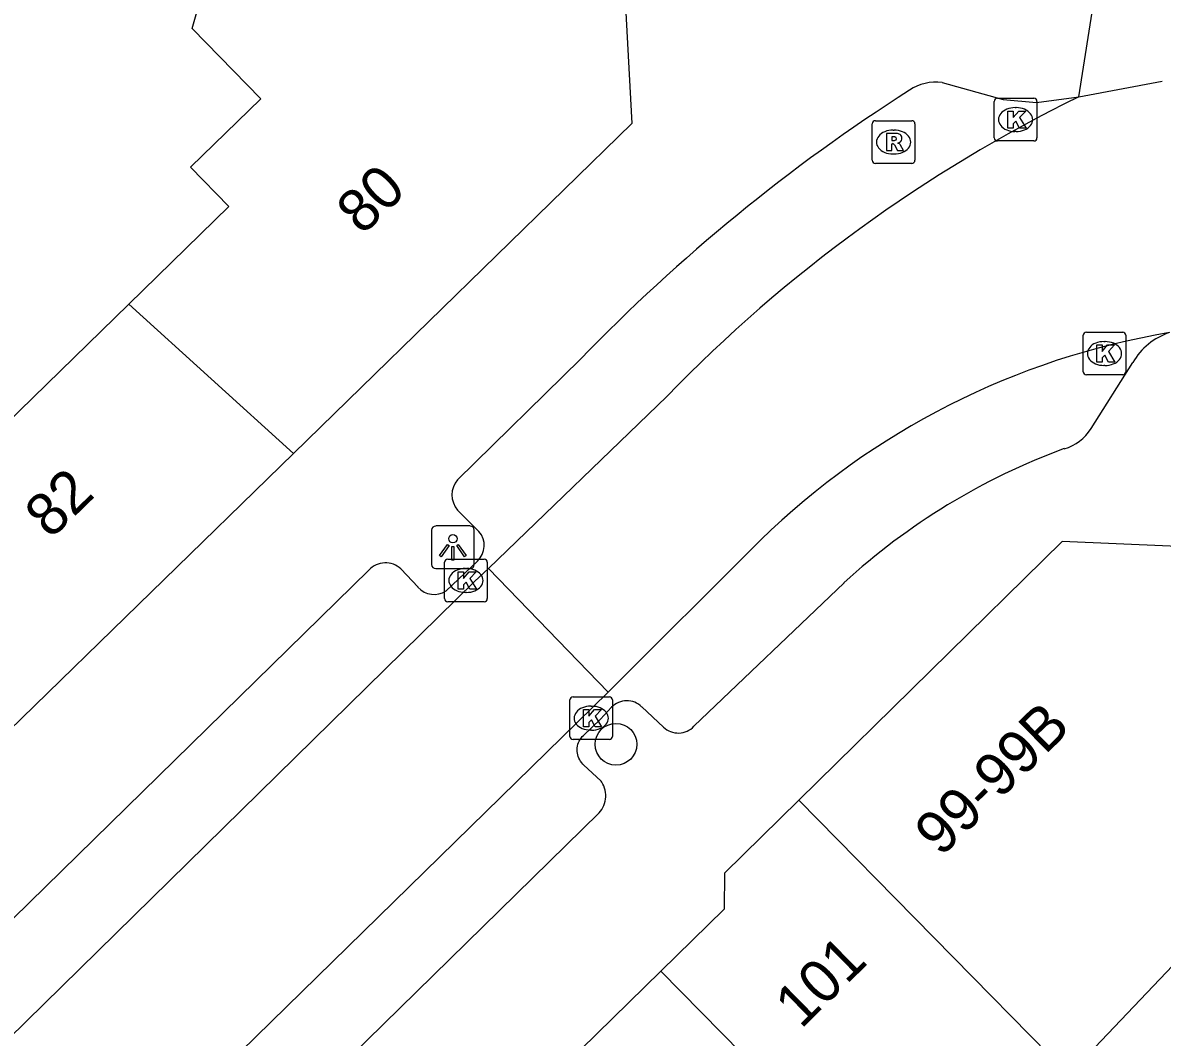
# Model space of a CAD drawing. Extents: x 160861 to 161308, y 384024 to 384878.
# Drawn here: x 161083.27 to 161109.96, y 384677.68 to 384701.45 of the extents above; entities that cross this region are included whole.
import ezdxf

# ---------------------------------------------------------------- set-up
doc = ezdxf.new("R2010")
doc.units = 0
for name, color, linetype in [('IMGEO_Boom', 7, 'Continuous'), ('IMGEO_Kolk', 7, 'Continuous'), ('IMGEO_Lichtpunt', 7, 'Continuous'), ('IMGEO_Pand', 7, 'Continuous'), ('IMGEO_Pand_nummerreeks', 7, 'Continuous'), ('IMGEO_Rijbaan_lokaal_gesloten', 7, 'Continuous'), ('IMGEO_Rijbaan_lokaal_open', 7, 'Continuous'), ('IMGEO_Rioolput', 7, 'Continuous'), ('IMGEO_Voetpad_open', 7, 'Continuous')]:
    doc.layers.add(name, color=color, linetype=linetype)

msp = doc.modelspace()

# ---------------------------------------------------------------- linework, layer by layer
at = {"layer": 'IMGEO_Boom'}
msp.add_circle((161097.165, 384684.545), 0.489, dxfattribs=at)
at = {"layer": 'IMGEO_Kolk'}
for p, q in [((161106.026, 384698.754), (161106.026, 384699.606)), ((161106.101, 384699.68), (161106.953, 384699.68)), ((161107.027, 384699.606), (161107.027, 384698.754)), ((161106.514, 384699.46), (161106.539, 384699.46)), ((161106.537, 384698.9), (161106.512, 384698.9)), ((161106.953, 384698.68), (161106.101, 384698.68)), ((161108.184, 384694.2), (161109.036, 384694.2)), ((161108.109, 384693.274), (161108.109, 384694.126)), ((161108.597, 384693.98), (161108.622, 384693.98)), ((161109.11, 384694.126), (161109.11, 384693.274)), ((161108.62, 384693.42), (161108.595, 384693.42)), ((161109.036, 384693.2), (161108.184, 384693.2)), ((161093.224, 384688.883), (161094.076, 384688.883)), ((161093.149, 384687.957), (161093.149, 384688.809)), ((161093.637, 384688.663), (161093.662, 384688.663)), ((161094.15, 384688.809), (161094.15, 384687.957)), ((161093.66, 384688.103), (161093.635, 384688.103)), ((161094.076, 384687.883), (161093.224, 384687.883)), ((161096.159, 384685.657), (161097.011, 384685.657)), ((161096.084, 384684.731), (161096.084, 384685.583)), ((161096.572, 384685.437), (161096.597, 384685.437)), ((161097.085, 384685.583), (161097.085, 384684.731)), ((161096.595, 384684.877), (161096.57, 384684.877)), ((161097.011, 384684.657), (161096.159, 384684.657))]:
    msp.add_line(p, q, dxfattribs=at)
for points in [[(161106.026, 384698.754), (161106.026, 384699.606)], [(161106.101, 384699.68), (161106.953, 384699.68)], [(161107.027, 384699.606), (161107.027, 384698.754)], [(161106.347, 384699.38), (161106.47, 384699.38), (161106.47, 384699.229), (161106.6, 384699.38), (161106.764, 384699.38), (161106.618, 384699.229), (161106.771, 384698.98), (161106.619, 384698.98), (161106.534, 384699.144), (161106.47, 384699.077), (161106.47, 384698.98), (161106.347, 384698.98), (161106.347, 384699.38)], [(161106.953, 384698.68), (161106.101, 384698.68)], [(161108.184, 384694.2), (161109.036, 384694.2)], [(161108.109, 384693.274), (161108.109, 384694.126)], [(161109.11, 384694.126), (161109.11, 384693.274)], [(161108.43, 384693.9), (161108.553, 384693.9), (161108.553, 384693.749), (161108.683, 384693.9), (161108.847, 384693.9), (161108.701, 384693.749), (161108.854, 384693.5), (161108.702, 384693.5), (161108.617, 384693.664), (161108.553, 384693.597), (161108.553, 384693.5), (161108.43, 384693.5), (161108.43, 384693.9)], [(161109.036, 384693.2), (161108.184, 384693.2)], [(161093.224, 384688.883), (161094.076, 384688.883)], [(161093.149, 384687.957), (161093.149, 384688.809)], [(161093.47, 384688.583), (161093.593, 384688.583), (161093.593, 384688.432), (161093.723, 384688.583), (161093.887, 384688.583), (161093.741, 384688.432), (161093.894, 384688.183), (161093.742, 384688.183), (161093.657, 384688.347), (161093.593, 384688.28), (161093.593, 384688.183), (161093.47, 384688.183), (161093.47, 384688.583)], [(161094.15, 384688.809), (161094.15, 384687.957)], [(161094.076, 384687.883), (161093.224, 384687.883)], [(161096.159, 384685.657), (161097.011, 384685.657)], [(161096.084, 384684.731), (161096.084, 384685.583)], [(161097.085, 384685.583), (161097.085, 384684.731)], [(161096.405, 384685.357), (161096.528, 384685.357), (161096.528, 384685.206), (161096.658, 384685.357), (161096.822, 384685.357), (161096.676, 384685.206), (161096.829, 384684.957), (161096.677, 384684.957), (161096.592, 384685.121), (161096.528, 384685.054), (161096.528, 384684.957), (161096.405, 384684.957), (161096.405, 384685.357)], [(161097.011, 384684.657), (161096.159, 384684.657)]]:
    msp.add_lwpolyline(points, dxfattribs=at)
for centre, start, end in [((161106.103, 384699.604), 91.552, 178.448), ((161106.103, 384699.604), 91.552, 178.448), ((161106.951, 384699.604), 1.552, 88.448), ((161106.951, 384699.604), 1.552, 88.448), ((161106.103, 384698.756), 181.552, 268.448), ((161106.103, 384698.756), 181.552, 268.448), ((161106.951, 384698.756), 271.552, 358.448), ((161106.951, 384698.756), 271.552, 358.448), ((161108.186, 384694.124), 91.552, 178.448), ((161108.186, 384694.124), 91.552, 178.448), ((161109.034, 384694.124), 1.552, 88.448), ((161109.034, 384694.124), 1.552, 88.448), ((161108.186, 384693.276), 181.552, 268.448), ((161108.186, 384693.276), 181.552, 268.448), ((161109.034, 384693.276), 271.552, 358.448), ((161109.034, 384693.276), 271.552, 358.448), ((161093.226, 384688.807), 91.552, 178.448), ((161093.226, 384688.807), 91.552, 178.448), ((161094.074, 384688.807), 1.552, 88.448), ((161094.074, 384688.807), 1.552, 88.448), ((161093.226, 384687.959), 181.552, 268.448), ((161093.226, 384687.959), 181.552, 268.448), ((161094.074, 384687.959), 271.552, 358.448), ((161094.074, 384687.959), 271.552, 358.448), ((161096.161, 384685.581), 91.552, 178.448), ((161096.161, 384685.581), 91.552, 178.448), ((161097.009, 384685.581), 1.552, 88.448), ((161097.009, 384685.581), 1.552, 88.448), ((161096.161, 384684.733), 181.552, 268.448), ((161096.161, 384684.733), 181.552, 268.448), ((161097.009, 384684.733), 271.552, 358.448), ((161097.009, 384684.733), 271.552, 358.448)]:
    msp.add_arc(centre, 0.0765, start, end, dxfattribs=at)
for centre, major_axis, ratio, start_param, end_param in [((161106.513, 384699.18), (-0.387, 0.002), 0.722429, 4.712389, 7.853982), ((161106.538, 384699.18), (-0.39, 0.002), 0.717154, 1.570796, 4.712389), ((161108.596, 384693.7), (-0.387, 0.002), 0.722429, 4.712389, 7.853982), ((161108.621, 384693.7), (-0.39, 0.002), 0.717154, 1.570796, 4.712389), ((161093.636, 384688.383), (-0.387, 0.002), 0.722429, 4.712389, 7.853982), ((161093.661, 384688.383), (-0.39, 0.002), 0.717154, 1.570796, 4.712389), ((161096.571, 384685.157), (-0.387, 0.002), 0.722429, 4.712389, 7.853982), ((161096.596, 384685.157), (-0.39, 0.002), 0.717154, 1.570796, 4.712389)]:
    msp.add_ellipse(centre, major_axis=major_axis, ratio=ratio, start_param=start_param, end_param=end_param, dxfattribs=at)
at = {"layer": 'IMGEO_Lichtpunt'}
for p, q in [((161093.749, 384689.659), (161092.941, 384689.659)), ((161093.749, 384689.659), (161092.941, 384689.659)), ((161092.847, 384689.564), (161092.847, 384688.757)), ((161092.847, 384689.564), (161092.847, 384688.757)), ((161093.843, 384688.757), (161093.843, 384689.564)), ((161093.843, 384688.757), (161093.843, 384689.564)), ((161092.941, 384688.663), (161093.749, 384688.663)), ((161092.941, 384688.663), (161093.749, 384688.663))]:
    msp.add_line(p, q, dxfattribs=at)
for points in [[(161093.221, 384689.228), (161093.26, 384689.2), (161093.072, 384688.938), (161093.034, 384688.965), (161093.221, 384689.228)], [(161093.323, 384689.18), (161093.37, 384689.18), (161093.37, 384688.858), (161093.323, 384688.858), (161093.323, 384689.18)], [(161093.433, 384689.2), (161093.471, 384689.227), (161093.658, 384688.965), (161093.619, 384688.937), (161093.433, 384689.2)]]:
    msp.add_lwpolyline(points, dxfattribs=at)
msp.add_circle((161093.346, 384689.362), 0.0994, dxfattribs=at)
for centre, start, end in [((161092.941, 384689.564), 90, 180), ((161092.941, 384689.564), 90, 180), ((161093.749, 384689.564), 0, 90), ((161093.749, 384689.564), 0, 90), ((161092.941, 384688.757), 180, 270), ((161092.941, 384688.757), 180, 270), ((161093.749, 384688.757), 270, 0), ((161093.749, 384688.757), 270, 360)]:
    msp.add_arc(centre, 0.0946, start, end, dxfattribs=at)
at = {"layer": 'IMGEO_Pand'}
for points in [[(161097.096, 384707.169), (161097.538, 384699.085), (161089.608, 384691.356)], [(161085.753, 384694.857), (161088.098, 384697.142), (161087.197, 384698.066), (161088.843, 384699.67), (161087.24, 384701.315), (161087.809, 384703.308)], [(161079.327, 384688.593), (161085.753, 384694.857)], [(161089.608, 384691.356), (161085.753, 384694.857)], [(161089.608, 384691.356), (161082.942, 384684.859)], [(161111.412, 384689.129), (161107.617, 384689.293), (161101.449, 384683.236)], [(161101.449, 384683.236), (161099.704, 384681.523), (161099.696, 384680.686), (161098.216, 384679.233)], [(161107.775, 384676.801), (161101.449, 384683.236)], [(161111.238, 384680.315), (161111.12, 384680.32), (161107.775, 384676.801)], [(161098.216, 384679.233), (161096.345, 384677.396), (161095.5, 384677.404), (161093.732, 384675.668)], [(161107.726, 384669.559), (161098.216, 384679.233)]]:
    msp.add_lwpolyline(points, dxfattribs=at)
at = {"layer": 'IMGEO_Rijbaan_lokaal_gesloten'}
for points in [[(161094.179, 384688.665), (161093.847, 384688.359), (161047.62, 384642.996), (161045.943, 384641.353)], [(161096.984, 384685.767), (161094.179, 384688.665)], [(161048.906, 384638.739), (161096.984, 384685.767)]]:
    msp.add_lwpolyline(points, dxfattribs=at)
at = {"layer": 'IMGEO_Rijbaan_lokaal_open'}
for points in [[(161108.011, 384699.714), (161109.961, 384700.078)], [(161094.179, 384688.665), (161098.356, 384692.696)], [(161096.984, 384685.767), (161100.553, 384689.329)]]:
    msp.add_lwpolyline(points, dxfattribs=at)
for centre, radius, start, end in [((161123.334, 384668.483), 34.788, 116.1342, 135.8909), ((161113.136, 384676.403), 18.039, 99.5884, 134.2287)]:
    msp.add_arc(centre, radius, start, end, dxfattribs=at)
at = {"layer": 'IMGEO_Rioolput'}
for p, q in [((161103.167, 384698.228), (161103.167, 384699.08)), ((161103.242, 384699.154), (161104.094, 384699.154)), ((161104.168, 384699.08), (161104.168, 384698.228)), ((161103.655, 384698.934), (161103.68, 384698.934)), ((161103.678, 384698.374), (161103.653, 384698.374)), ((161104.094, 384698.154), (161103.242, 384698.154))]:
    msp.add_line(p, q, dxfattribs=at)
for points in [[(161103.167, 384698.228), (161103.167, 384699.08)], [(161103.242, 384699.154), (161104.094, 384699.154)], [(161104.168, 384699.08), (161104.168, 384698.228)], [(161103.756, 384698.852), (161103.504, 384698.854), (161103.504, 384698.454)], [(161103.682, 384698.773), (161103.628, 384698.773), (161103.628, 384698.692)], [(161103.504, 384698.454), (161103.628, 384698.454), (161103.628, 384698.616), (161103.639, 384698.616)], [(161103.628, 384698.692), (161103.68, 384698.692)], [(161103.686, 384698.587), (161103.757, 384698.454), (161103.897, 384698.454), (161103.832, 384698.58)], [(161104.094, 384698.154), (161103.242, 384698.154)]]:
    msp.add_lwpolyline(points, dxfattribs=at)
for centre, radius, start, end in [((161103.244, 384699.078), 0.0765, 91.552, 178.448), ((161103.244, 384699.078), 0.0765, 91.552, 178.448), ((161104.092, 384699.078), 0.0765, 1.552, 88.448), ((161104.092, 384699.078), 0.0765, 1.552, 88.448), ((161103.688, 384698.677), 0.0964, 77.0061, 93.1865), ((161103.702, 384698.734), 0.0378, 276.6634, 79.6772), ((161103.755, 384698.742), 0.109, 350.3612, 89.416), ((161103.638, 384698.563), 0.0533, 26.0293, 88.6989), ((161103.664, 384698.881), 0.19, 274.7715, 282.9687), ((161103.753, 384698.742), 0.112, 277.5842, 350.9817), ((161103.737, 384698.527), 0.108, 29.5134, 73.7905), ((161103.244, 384698.23), 0.0765, 181.552, 268.448), ((161103.244, 384698.23), 0.0765, 181.552, 268.448), ((161104.092, 384698.23), 0.0765, 271.552, 358.448), ((161104.092, 384698.23), 0.0765, 271.552, 358.448)]:
    msp.add_arc(centre, radius, start, end, dxfattribs=at)
for centre, major_axis, ratio, start_param, end_param in [((161103.654, 384698.654), (-0.387, 0.002), 0.722429, 4.712389, 7.853982), ((161103.679, 384698.654), (-0.39, 0.002), 0.717154, 1.570796, 4.712389)]:
    msp.add_ellipse(centre, major_axis=major_axis, ratio=ratio, start_param=start_param, end_param=end_param, dxfattribs=at)
at = {"layer": 'IMGEO_Voetpad_open'}
for points in [[(161108.011, 384699.714), (161108.517, 384702.943)], [(161104.804, 384700.047), (161106.233, 384699.652), (161107.018, 384699.583), (161108.011, 384699.714)], [(161093.451, 384690.742), (161096.334, 384693.567)], [(161108.293, 384691.946), (161109.275, 384693.49)], [(161093.954, 384689.529), (161093.451, 384690.029)], [(161080.008, 384677.5), (161091.379, 384688.627)], [(161092.125, 384688.655), (161092.527, 384688.225)], [(161093.184, 384688.14), (161093.92, 384688.837)], [(161098.991, 384684.968), (161102.507, 384688.329)], [(161085.497, 384671.893), (161096.768, 384682.94), (161096.802, 384682.979), (161096.832, 384683.021), (161096.859, 384683.066), (161096.881, 384683.113), (161096.899, 384683.161), (161096.913, 384683.212), (161096.922, 384683.263), (161096.927, 384683.314), (161096.927, 384683.366), (161096.922, 384683.418), (161096.913, 384683.469), (161096.899, 384683.519), (161096.88, 384683.568), (161096.858, 384683.614), (161096.831, 384683.659), (161096.816, 384683.681), (161096.406, 384684.067), (161096.39, 384684.082), (161096.362, 384684.113), (161096.337, 384684.146), (161096.315, 384684.181), (161096.296, 384684.218), (161096.28, 384684.257), (161096.268, 384684.297), (161096.26, 384684.338), (161096.255, 384684.379), (161096.254, 384684.421), (161096.257, 384684.463), (161096.263, 384684.504), (161096.273, 384684.544), (161096.287, 384684.584), (161096.304, 384684.622), (161096.324, 384684.658), (161096.348, 384684.692), (161096.375, 384684.724), (161096.404, 384684.754), (161096.799, 384685.132), (161097.063, 384685.411)], [(161097.767, 384685.424), (161098.278, 384684.948)]]:
    msp.add_lwpolyline(points, dxfattribs=at)
for centre, radius, start, end in [((161127.003, 384663.928), 42.651, 122.5747, 135.9782), ((161104.653, 384698.967), 1.09, 82.0275, 124.2026), ((161110.609, 384692.732), 1.534, 108.1535, 150.3962), ((161107.389, 384692.487), 1.054, 285.2952, 329.0863), ((161113.044, 384676.832), 15.596, 110.1698, 132.5059), ((161093.883, 384690.386), 0.56, 140.499, 219.501), ((161093.586, 384689.2), 0.493, 312.5599, 41.8144), ((161091.766, 384688.27), 0.527, 47.0171, 137.2819), ((161092.904, 384688.558), 0.503, 221.4391, 303.8174), ((161097.421, 384685.068), 0.496, 45.8629, 136.2529), ((161098.625, 384685.313), 0.504, 226.5127, 316.7008)]:
    msp.add_arc(centre, radius, start, end, dxfattribs=at)

# ---------------------------------------------------------------- texts
at = {"layer": 'IMGEO_Pand_nummerreeks'}
for s, rotation, p in [('80', 44.2646, (161091.225, 384696.451)), ('82', 44.2644, (161083.923, 384689.333)), ('99-99B', 44.4981, (161104.775, 384681.885)), ('101', 44.473, (161101.5, 384677.861))]:
    msp.add_text(s, height=1, rotation=rotation, dxfattribs=at).set_placement(p)

doc.saveas('drawing.dxf')
